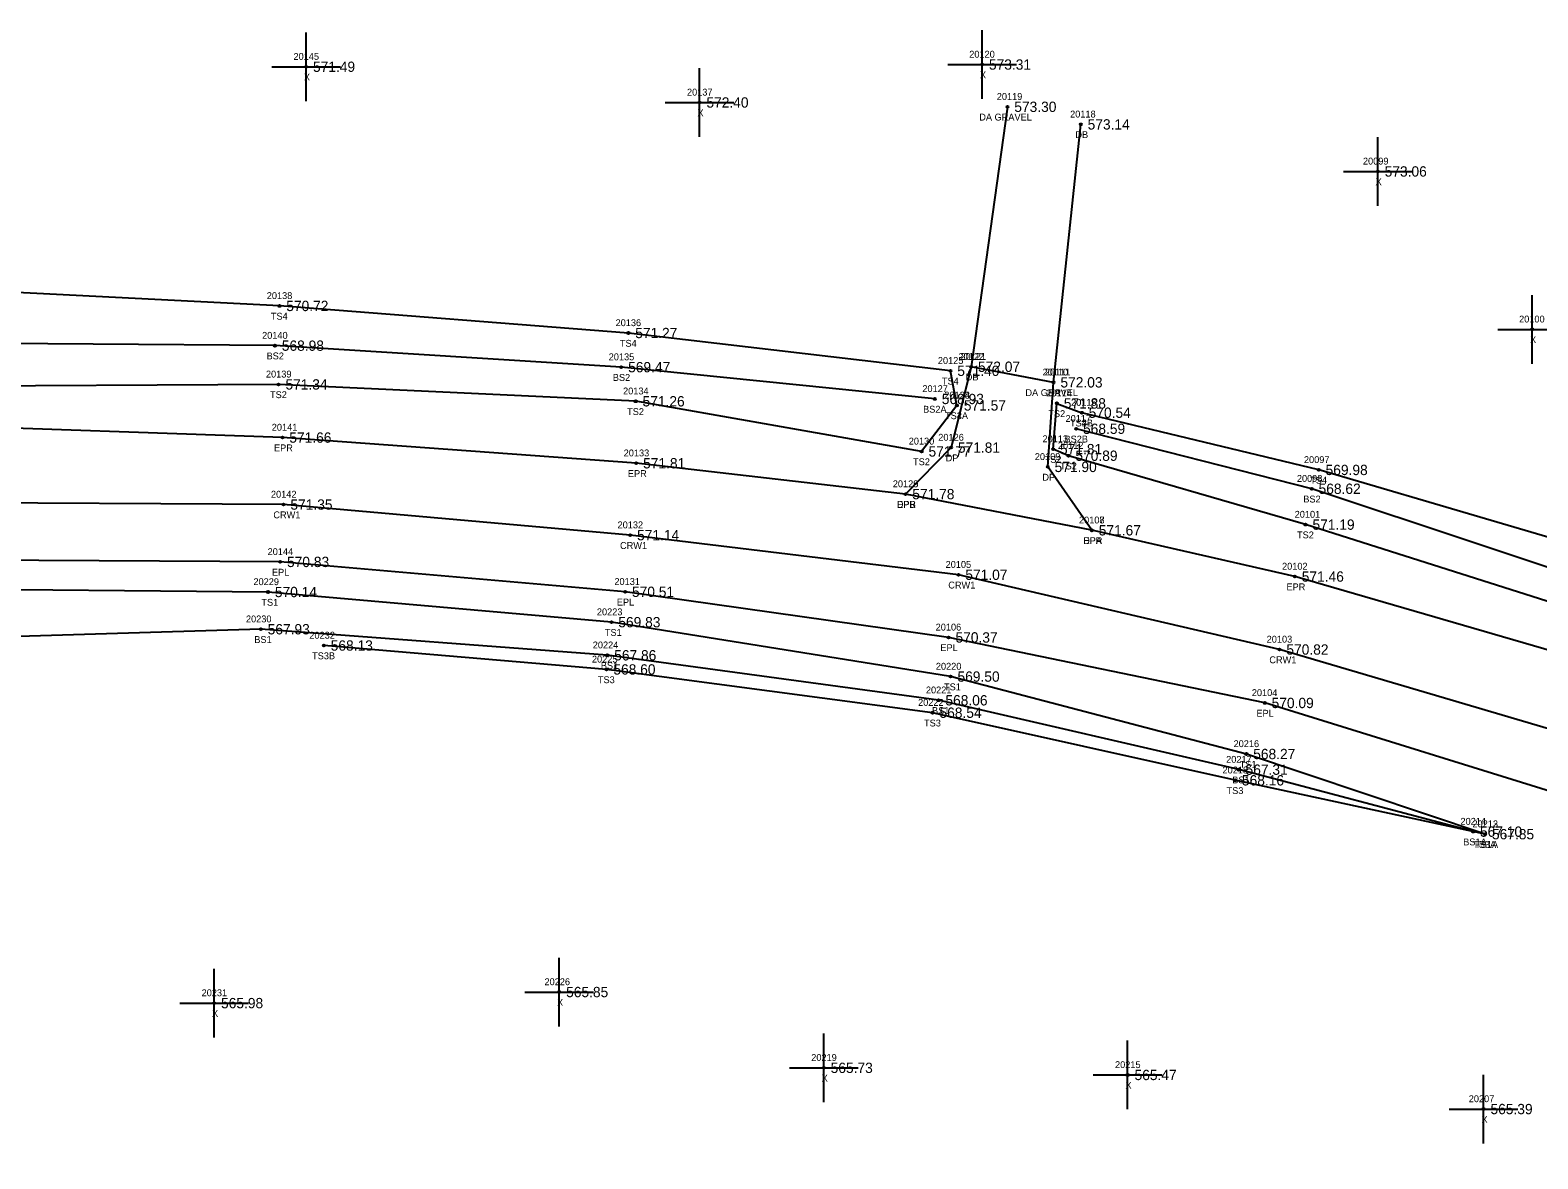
# Model space of a CAD drawing. Extents: x 1530159 to 1531652, y 877045 to 877724.
# Drawn here: x 1531149.1 to 1531368.6, y 877186 to 877350.2 of the extents above; entities that cross this region are included whole.
import ezdxf

# ---------------------------------------------------------------- set-up
doc = ezdxf.new("R2010")
doc.units = 0
for name, color, linetype in [('RD_DTM_BkLn1', 7, 'Continuous'), ('RD_DTM_BkLn2', 7, 'Continuous'), ('RD_DTM_BkLn_txCode', 7, 'Continuous'), ('RD_EX_Driveway', 7, 'Continuous'), ('RD_EX_Driveway_txCode', 7, 'Continuous'), ('RD_EX_Misc', 7, 'Continuous'), ('RD_EX_Misc_txCode', 7, 'Continuous'), ('RD_EX_Road', 7, 'Continuous'), ('RD_EX_Road_txCode', 7, 'Continuous'), ('RD_EX_TX_Driveway_ELEV', 7, 'Continuous'), ('RD_EX_TX_Misc_ELEV', 7, 'Continuous'), ('RD_EX_TX_Road_ELEV', 7, 'Continuous'), ('RD_HC_Survey_ELEV', 7, 'Continuous'), ('RD_HC_Survey_txCode', 7, 'Continuous'), ('RD_SMD_Locator', 7, 'Continuous')]:
    doc.layers.add(name, color=color, linetype=linetype)

msp = doc.modelspace()

# ---------------------------------------------------------------- linework, layer by layer
at = {"layer": 'RD_DTM_BkLn1'}
msp.add_lwpolyline([(1531601.44, 877127.51), (1531558.79, 877158.11), (1531516.37, 877185.16), (1531470.77, 877211.58), (1531426.8, 877229.22), (1531379.86, 877245.66), (1531330.99, 877260.09), (1531284.24, 877270.97), (1531236.44, 877276.73), (1531185.96, 877281.19), (1531132.29, 877281.48), (1531081.11, 877280.78), (1531028.25, 877278.4), (1530978.85, 877276.13), (1530941.18, 877274.78)], dxfattribs=at)
at = {"layer": 'RD_DTM_BkLn2'}
for points in [[(1531284.02, 877295.62), (1531283.07, 877300.66), (1531236.17, 877306.16), (1531185.36, 877310.1), (1531137.54, 877312.53), (1531080.59, 877304.96)], [(1531284.02, 877295.62), (1531278.88, 877288.92), (1531237.24, 877296.22), (1531185.24, 877298.68), (1531132.13, 877298.36), (1531081.04, 877299.23), (1531072.11, 877310.45)], [(1531280.81, 877296.56), (1531235.14, 877301.19), (1531184.71, 877304.32), (1531131.72, 877304.73), (1531080.59, 877304.96)], [(1531409.41, 877256.25), (1531384.28, 877262.57), (1531334.79, 877278.27), (1531300.27, 877288.3), (1531298.03, 877289.26), (1531298.58, 877295.92), (1531302.2, 877294.56)], [(1531409.41, 877256.25), (1531412.58, 877262.39), (1531411.23, 877265.27), (1531386.92, 877271.48), (1531336.7, 877286.23), (1531302.2, 877294.56)], [(1531409.08, 877261.02), (1531384.89, 877267.15), (1531335.68, 877283.49), (1531301.38, 877292.22)], [(1531360.93, 877233.21), (1531326.16, 877244.88), (1531283.1, 877256.15), (1531233.71, 877264.07), (1531183.7, 877268.46), (1531131.39, 877268.9), (1531078.21, 877267.99), (1531030.38, 877264.81), (1530978.79, 877263), (1530945.28, 877257.44), (1530934.34, 877257.51), (1530931.22, 877260.12)], [(1531359.18, 877233.58), (1531325.05, 877242.6), (1531281.34, 877252.7), (1531233.11, 877259.25), (1531182.65, 877263.04), (1531132.85, 877261.57), (1531078.42, 877261.15), (1531032.11, 877253.2), (1530980.63, 877245.27), (1530948.73, 877252.16)], [(1531360.93, 877233.21), (1531324.52, 877241.05), (1531280.48, 877250.89), (1531232.99, 877257.19), (1531191.83, 877260.67)]]:
    msp.add_lwpolyline(points, dxfattribs=at)
at = {"layer": 'RD_EX_Driveway'}
for p, q in [((1531291.37, 877339.09), (1531286.08, 877301.25)), ((1531298.09, 877298.98), (1531302.05, 877336.53))]:
    msp.add_line(p, q, dxfattribs=at)
msp.add_lwpolyline([(1531303.67, 877277.44), (1531297.24, 877286.67), (1531298.09, 877298.98), (1531286.08, 877301.25), (1531283.16, 877289.48), (1531276.52, 877282.71)], dxfattribs=at)
at = {"layer": 'RD_EX_Misc'}
for p, q in [((1531189.25, 877339.92), (1531189.25, 877349.92)), ((1531287.68, 877340.24), (1531287.68, 877350.24)), ((1531184.25, 877344.92), (1531194.25, 877344.92)), ((1531246.54, 877334.72), (1531246.54, 877344.72)), ((1531282.68, 877345.24), (1531292.68, 877345.24)), ((1531241.54, 877339.72), (1531251.54, 877339.72)), ((1531345.3, 877324.68), (1531345.3, 877334.68)), ((1531340.3, 877329.68), (1531350.3, 877329.68)), ((1531367.79, 877301.69), (1531367.79, 877311.69)), ((1531362.79, 877306.69), (1531372.79, 877306.69)), ((1531226.11, 877205.23), (1531226.11, 877215.23)), ((1531175.86, 877203.62), (1531175.86, 877213.62)), ((1531221.11, 877210.23), (1531231.11, 877210.23)), ((1531170.86, 877208.62), (1531180.86, 877208.62)), ((1531264.63, 877194.2), (1531264.63, 877204.2)), ((1531308.88, 877193.16), (1531308.88, 877203.16)), ((1531259.63, 877199.2), (1531269.63, 877199.2)), ((1531303.88, 877198.16), (1531313.88, 877198.16)), ((1531360.71, 877188.2), (1531360.71, 877198.2)), ((1531355.71, 877193.2), (1531365.71, 877193.2))]:
    msp.add_line(p, q, dxfattribs=at)
at = {"layer": 'RD_EX_Road'}
for points in [[(1531606.64, 877133.84), (1531579.15, 877155.05), (1531564.87, 877165.27), (1531535.22, 877186.03), (1531511.53, 877200.27), (1531474.57, 877218.9), (1531430.45, 877239.35), (1531404.48, 877249.38), (1531382.32, 877256.43), (1531333.23, 877270.71), (1531303.67, 877277.44), (1531276.52, 877282.71), (1531237.32, 877287.2), (1531185.8, 877290.94), (1531132.61, 877292.77), (1531081.11, 877292.38), (1531038.69, 877288.67), (1530976.42, 877285.45), (1530941.06, 877284.26)], [(1531595.27, 877120.27), (1531553.56, 877149.9), (1531509.97, 877177.57), (1531465.94, 877201.73), (1531423.65, 877222), (1531376.09, 877237.68), (1531328.84, 877252.31), (1531282.81, 877261.85), (1531235.7, 877268.49), (1531185.47, 877272.84), (1531132.72, 877273.12), (1531080.2, 877271.87), (1531029.21, 877269.53), (1530978.47, 877268.32), (1530945.95, 877265.93), (1530941.45, 877262.44)]]:
    msp.add_lwpolyline(points, dxfattribs=at)
at = {"layer": 'RD_SMD_Locator'}
for centre in [(1531189.25, 877344.92), (1531287.68, 877345.24), (1531246.54, 877339.72), (1531291.37, 877339.09), (1531302.05, 877336.53), (1531345.3, 877329.68), (1531185.36, 877310.1), (1531236.17, 877306.16), (1531367.79, 877306.69), (1531184.71, 877304.32), (1531235.14, 877301.19), (1531283.07, 877300.66), (1531286.08, 877301.25), (1531286.08, 877301.25), (1531185.24, 877298.68), (1531298.09, 877298.98), (1531298.09, 877298.98), (1531237.24, 877296.22), (1531280.81, 877296.56), (1531284.02, 877295.62), (1531284.02, 877295.62), (1531298.58, 877295.92), (1531302.2, 877294.56), (1531302.2, 877294.56), (1531185.8, 877290.94), (1531301.38, 877292.22), (1531278.88, 877288.92), (1531283.16, 877289.48), (1531298.03, 877289.26), (1531300.27, 877288.3), (1531237.32, 877287.2), (1531297.24, 877286.67), (1531336.7, 877286.23), (1531276.52, 877282.71), (1531276.52, 877282.71), (1531335.68, 877283.49), (1531185.96, 877281.19), (1531303.67, 877277.44), (1531303.67, 877277.44), (1531334.79, 877278.27), (1531236.44, 877276.73), (1531185.47, 877272.84), (1531284.24, 877270.97), (1531333.23, 877270.71), (1531183.7, 877268.46), (1531235.7, 877268.49), (1531233.71, 877264.07), (1531182.65, 877263.04), (1531191.83, 877260.67), (1531282.81, 877261.85), (1531330.99, 877260.09), (1531233.11, 877259.25), (1531232.99, 877257.19), (1531283.1, 877256.15), (1531280.48, 877250.89), (1531281.34, 877252.7), (1531328.84, 877252.31), (1531326.16, 877244.88), (1531325.05, 877242.6), (1531324.52, 877241.05), (1531359.18, 877233.58), (1531360.93, 877233.21), (1531360.93, 877233.21), (1531226.11, 877210.23), (1531175.86, 877208.62), (1531264.63, 877199.2), (1531308.88, 877198.16), (1531360.71, 877193.2)]:
    msp.add_circle(centre, 0.15, dxfattribs=at)

# ---------------------------------------------------------------- texts
at = {"layer": 'RD_DTM_BkLn_txCode'}
for s, p in [('20138', (1531183.52, 877311.1)), ('TS4', (1531184.11, 877308.1)), ('20136', (1531234.31, 877307.16)), ('20140', (1531182.84, 877305.32)), ('TS4', (1531234.93, 877304.16)), ('BS2', (1531183.49, 877302.32)), ('20135', (1531233.31, 877302.19)), ('20125', (1531281.24, 877301.66)), ('20139', (1531183.4, 877299.68)), ('BS2', (1531233.91, 877299.19)), ('TS4', (1531281.83, 877298.66)), ('TS2', (1531183.99, 877296.68)), ('20134', (1531235.4, 877297.22)), ('20127', (1531278.98, 877297.56)), ('20123', (1531282.18, 877296.62)), ('20124', (1531282.18, 877296.62)), ('20114', (1531297.03, 877296.92)), ('TS2', (1531235.99, 877294.22)), ('BS2A', (1531279.09, 877294.56)), ('20116', (1531300.63, 877295.56)), ('20115', (1531300.65, 877295.56)), ('TS2A', (1531282.29, 877293.62)), ('TS4A', (1531282.29, 877293.62)), ('TS2', (1531297.33, 877293.92)), ('20117', (1531299.83, 877293.22)), ('TS2B', (1531300.48, 877292.56)), ('TS4B', (1531300.48, 877292.56)), ('20130', (1531277, 877289.92)), ('20113', (1531296.48, 877290.26)), ('BS2B', (1531299.68, 877290.22)), ('20112', (1531298.72, 877289.3)), ('TS2', (1531277.63, 877286.92)), ('TS2', (1531296.79, 877287.26)), ('TS2', (1531299.03, 877286.3)), ('20097', (1531334.55, 877287.23)), ('20098', (1531333.52, 877284.49)), ('TS4', (1531335.46, 877284.23)), ('BS2', (1531334.45, 877281.49)), ('20101', (1531333.2, 877279.27)), ('TS2', (1531333.54, 877276.27)), ('20229', (1531181.58, 877269.46)), ('TS1', (1531182.74, 877266.46)), ('20230', (1531180.49, 877264.04)), ('20223', (1531231.59, 877265.07)), ('BS1', (1531181.7, 877261.04)), ('20232', (1531189.72, 877261.67)), ('TS1', (1531232.75, 877262.07)), ('20224', (1531230.99, 877260.25)), ('TS3B', (1531190.12, 877258.67)), ('20225', (1531230.87, 877258.19)), ('BS1', (1531232.16, 877257.25)), ('20220', (1531280.95, 877257.15)), ('TS3', (1531231.74, 877255.19)), ('20221', (1531279.5, 877253.7)), ('TS1', (1531282.14, 877254.15)), ('20222', (1531278.36, 877251.89)), ('BS1', (1531280.39, 877250.7)), ('TS3', (1531279.23, 877248.89)), ('20216', (1531324.3, 877245.88)), ('20217', (1531323.22, 877243.6)), ('20218', (1531322.69, 877242.05)), ('TS1', (1531325.2, 877242.88)), ('TS3', (1531323.28, 877239.05)), ('BS1', (1531324.11, 877240.6)), ('20214', (1531357.34, 877234.58)), ('20212', (1531359.09, 877234.21)), ('20213', (1531359.09, 877234.21)), ('BS1A', (1531357.74, 877231.58)), ('TS3A', (1531359.2, 877231.21)), ('TS1A', (1531359.48, 877231.21))]:
    msp.add_text(s, height=1, dxfattribs=at).set_placement(p)
at = {"layer": 'RD_EX_Driveway_txCode'}
for s, p in [('20119', (1531289.82, 877340.09)), ('DA GRAVEL', (1531287.27, 877337.09)), ('20118', (1531300.5, 877337.53)), ('DB', (1531301.27, 877334.53)), ('20122', (1531284.25, 877302.25)), ('20121', (1531284.53, 877302.25)), ('DB', (1531285.3, 877299.25)), ('DP', (1531285.3, 877299.25)), ('20110', (1531296.5, 877299.98)), ('20111', (1531296.82, 877299.98)), ('DA GRAVEL', (1531293.99, 877296.98)), ('DP', (1531297.31, 877296.98)), ('20126', (1531281.3, 877290.48)), ('DP', (1531282.38, 877287.48)), ('20109', (1531295.36, 877287.67)), ('20128', (1531274.68, 877283.71)), ('DP', (1531296.46, 877284.67)), ('DPB', (1531275.27, 877280.71)), ('20108', (1531301.79, 877278.44)), ('DPA', (1531302.4, 877275.44))]:
    msp.add_text(s, height=1, dxfattribs=at).set_placement(p)
at = {"layer": 'RD_EX_Misc_txCode'}
for s, p in [('20145', (1531187.41, 877345.92)), ('20120', (1531285.81, 877346.24)), ('X', (1531188.93, 877342.92)), ('X', (1531287.37, 877343.24)), ('20137', (1531244.71, 877340.72)), ('X', (1531246.23, 877337.72)), ('20099', (1531343.14, 877330.68)), ('X', (1531344.98, 877327.68)), ('20100', (1531365.88, 877307.69)), ('X', (1531367.48, 877304.69)), ('20226', (1531223.96, 877211.23)), ('20231', (1531174.03, 877209.62)), ('X', (1531175.55, 877206.62)), ('X', (1531225.79, 877208.23)), ('20219', (1531262.8, 877200.2)), ('20215', (1531307.04, 877199.16)), ('X', (1531264.32, 877197.2)), ('X', (1531308.56, 877196.16)), ('20207', (1531358.55, 877194.2)), ('X', (1531360.4, 877191.2))]:
    msp.add_text(s, height=1, dxfattribs=at).set_placement(p)
at = {"layer": 'RD_EX_Road_txCode'}
for s, p in [('20141', (1531184.25, 877291.94)), ('EPR', (1531184.57, 877288.94)), ('20133', (1531235.49, 877288.2)), ('EPR', (1531236.1, 877285.2)), ('20129', (1531274.68, 877283.71)), ('EPR', (1531275.29, 877280.71)), ('20107', (1531301.79, 877278.44)), ('EPR', (1531302.44, 877275.44)), ('20144', (1531183.64, 877273.84)), ('EPL', (1531184.27, 877270.84)), ('20102', (1531331.36, 877271.71)), ('20131', (1531234.14, 877269.49)), ('EPR', (1531332, 877268.71)), ('EPL', (1531234.49, 877266.49)), ('20106', (1531280.92, 877262.85)), ('EPL', (1531281.61, 877259.85)), ('20104', (1531326.96, 877253.31)), ('EPL', (1531327.63, 877250.31))]:
    msp.add_text(s, height=1, dxfattribs=at).set_placement(p)
at = {"layer": 'RD_EX_TX_Driveway_ELEV'}
for s, p in [('573.30', (1531292.37, 877338.34)), ('573.14', (1531303.05, 877335.78)), ('572.07', (1531287.08, 877300.5)), ('572.07', (1531287.08, 877300.5)), ('572.03', (1531299.09, 877298.23)), ('572.03', (1531299.09, 877298.23)), ('571.81', (1531284.16, 877288.73)), ('571.90', (1531298.24, 877285.92)), ('571.78', (1531277.52, 877281.96)), ('571.67', (1531304.67, 877276.69))]:
    msp.add_text(s, height=1.5, dxfattribs=at).set_placement(p)
at = {"layer": 'RD_EX_TX_Misc_ELEV'}
for s, p in [('571.49', (1531190.25, 877344.17)), ('573.31', (1531288.68, 877344.49)), ('572.40', (1531247.54, 877338.97)), ('573.06', (1531346.3, 877328.93)), ('570.72', (1531186.36, 877309.35)), ('571.27', (1531237.17, 877305.41)), ('568.98', (1531185.71, 877303.57)), ('569.47', (1531236.14, 877300.44)), ('571.34', (1531186.24, 877297.93)), ('571.40', (1531284.07, 877299.91)), ('568.93', (1531281.81, 877295.81)), ('571.26', (1531238.24, 877295.47)), ('571.57', (1531285.02, 877294.87)), ('571.57', (1531285.02, 877294.87)), ('571.88', (1531299.58, 877295.17)), ('570.54', (1531303.2, 877293.81)), ('570.54', (1531303.2, 877293.81)), ('568.59', (1531302.38, 877291.47)), ('571.77', (1531279.88, 877288.17)), ('571.81', (1531299.03, 877288.51)), ('570.89', (1531301.27, 877287.55)), ('569.98', (1531337.7, 877285.48)), ('568.62', (1531336.68, 877282.74)), ('571.19', (1531335.79, 877277.52)), ('570.14', (1531184.7, 877267.71)), ('569.83', (1531234.71, 877263.32)), ('567.93', (1531183.65, 877262.29)), ('568.13', (1531192.83, 877259.92)), ('567.86', (1531234.11, 877258.5)), ('568.60', (1531233.99, 877256.44)), ('569.50', (1531284.1, 877255.4)), ('568.06', (1531282.34, 877251.95)), ('568.54', (1531281.48, 877250.14)), ('568.27', (1531327.16, 877244.13)), ('567.31', (1531326.05, 877241.85)), ('568.16', (1531325.52, 877240.3)), ('567.10', (1531360.18, 877232.83)), ('567.85', (1531361.93, 877232.46)), ('567.85', (1531361.93, 877232.46)), ('565.98', (1531176.86, 877207.87)), ('565.85', (1531227.11, 877209.48)), ('565.73', (1531265.63, 877198.45)), ('565.47', (1531309.88, 877197.41)), ('565.39', (1531361.71, 877192.45))]:
    msp.add_text(s, height=1.5, dxfattribs=at).set_placement(p)
at = {"layer": 'RD_EX_TX_Road_ELEV'}
for s, p in [('571.66', (1531186.8, 877290.19)), ('571.81', (1531238.32, 877286.45)), ('571.78', (1531277.52, 877281.96)), ('571.67', (1531304.67, 877276.69)), ('570.83', (1531186.47, 877272.09)), ('571.46', (1531334.23, 877269.96)), ('570.51', (1531236.7, 877267.74)), ('570.37', (1531283.81, 877261.1)), ('570.09', (1531329.84, 877251.56))]:
    msp.add_text(s, height=1.5, dxfattribs=at).set_placement(p)
at = {"layer": 'RD_HC_Survey_ELEV'}
for s, p in [('571.35', (1531186.96, 877280.44)), ('571.14', (1531237.44, 877275.98)), ('571.07', (1531285.24, 877270.22)), ('570.82', (1531331.99, 877259.34))]:
    msp.add_text(s, height=1.5, dxfattribs=at).set_placement(p)
at = {"layer": 'RD_HC_Survey_txCode'}
for s, p in [('20142', (1531184.13, 877282.19)), ('CRW1', (1531184.48, 877279.19)), ('20132', (1531234.6, 877277.73)), ('CRW1', (1531234.96, 877274.73)), ('20105', (1531282.37, 877271.97)), ('CRW1', (1531282.76, 877268.97)), ('20103', (1531329.12, 877261.09)), ('CRW1', (1531329.51, 877258.09))]:
    msp.add_text(s, height=1, dxfattribs=at).set_placement(p)

doc.saveas('drawing.dxf')
